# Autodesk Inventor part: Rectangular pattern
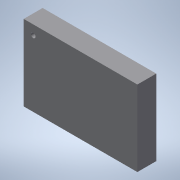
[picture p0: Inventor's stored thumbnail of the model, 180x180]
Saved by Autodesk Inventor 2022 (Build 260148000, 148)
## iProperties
Created: 2013-12
Part Number: Rectangular pattern
Material: Generic
Document SubType Name: Modeling
Designer: John
Density: 1 g/cm^3
Appearance: Default
Author: John
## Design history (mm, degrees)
sketch "Sketch1"
  geometry: L1 (0, 0)-(152.4, 0); L2 (152.4, 0)-(152.4, 101.6); L3 (152.4, 101.6)-(0, 101.6); L4 (0, 101.6)-(0, 0)
  constraints: 8 end point, 2 parallel, 1 horizontal, 1 perpendicular
  dimensions: "d0" = 152.4 distance of L3.end L2.end; "d1" = 101.6 distance of L2.end L1.end
extrude "Extrusion1" new body sketch "Sketch1" distance "d2" = 25.4; taper "d3" = 0 deg
sketch "Sketch2"
  geometry: L1 (152.4, 101.6)-(0, 101.6) reference; L2 (0, 101.6)-(0, 0) reference; C1 r 3.175 at (12.7, 88.9)
  constraints: 1 centre point
  dimensions: "d4" = 6.35 diameter of C1; "d5" = 12.7 distance from line of L2 C1.centre; "d6" = 12.7 distance from line of L1 C1.centre
extrude "Extrusion2" cut sketch "Sketch2" extent not by distance; stored distance "d7" = 25.4; taper "d8" = 0 deg
body "Solid1"
